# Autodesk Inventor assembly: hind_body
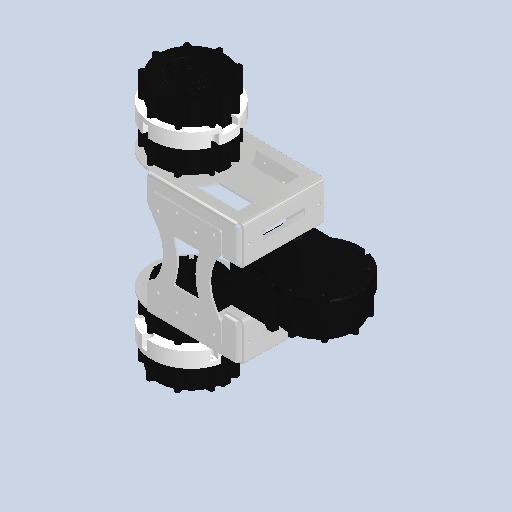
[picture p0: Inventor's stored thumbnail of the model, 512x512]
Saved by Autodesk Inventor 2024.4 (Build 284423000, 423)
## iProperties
Created: 2026-01
Part Number: hind_body
Document SubType Name: Assembly
Designer: AdminForWorker
Title: hind_body v18
Author: AdminForWorker
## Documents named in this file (7)
- c:\worker\convert-fusion-r06-cosv3\tmp\job-1\20\temp\files\5a45f03c-e7c3-4700-b116-8c6d3caf3368\377022f8-cd84-4795-9de6-8f4e5b64e336.iam
- c:\worker\convert-fusion-r06-cosv3\tmp\job-1\20\temp\files\5a45f03c-e7c3-4700-b116-8c6d3caf3368\body_assembly.iam
- c:\worker\convert-fusion-r06-cosv3\tmp\job-1\20\temp\files\5a45f03c-e7c3-4700-b116-8c6d3caf3368\leg_connector v1.ipt
- c:\worker\convert-fusion-r06-cosv3\tmp\job-1\20\temp\files\5a45f03c-e7c3-4700-b116-8c6d3caf3368\CyberGear.ipt
- c:\worker\convert-fusion-r06-cosv3\tmp\job-1\20\temp\files\5a45f03c-e7c3-4700-b116-8c6d3caf3368\CyberGear (1).ipt
- c:\worker\convert-fusion-r06-cosv3\tmp\job-1\20\temp\files\5a45f03c-e7c3-4700-b116-8c6d3caf3368\CyberGear (2).ipt
- c:\worker\convert-fusion-r06-cosv3\tmp\job-1\20\temp\files\5a45f03c-e7c3-4700-b116-8c6d3caf3368\hind_spine v1.iam
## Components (8 placed, 6 different names)
1. body_assembly:1 [sub-assembly]
2. leg_connector v1:1
3. CyberGear:1
4. CyberGear:2
5. CyberGear (1):1
6. CyberGear (2):1
7. leg_connector v1:2
8. hind_spine v1:1 [sub-assembly]
